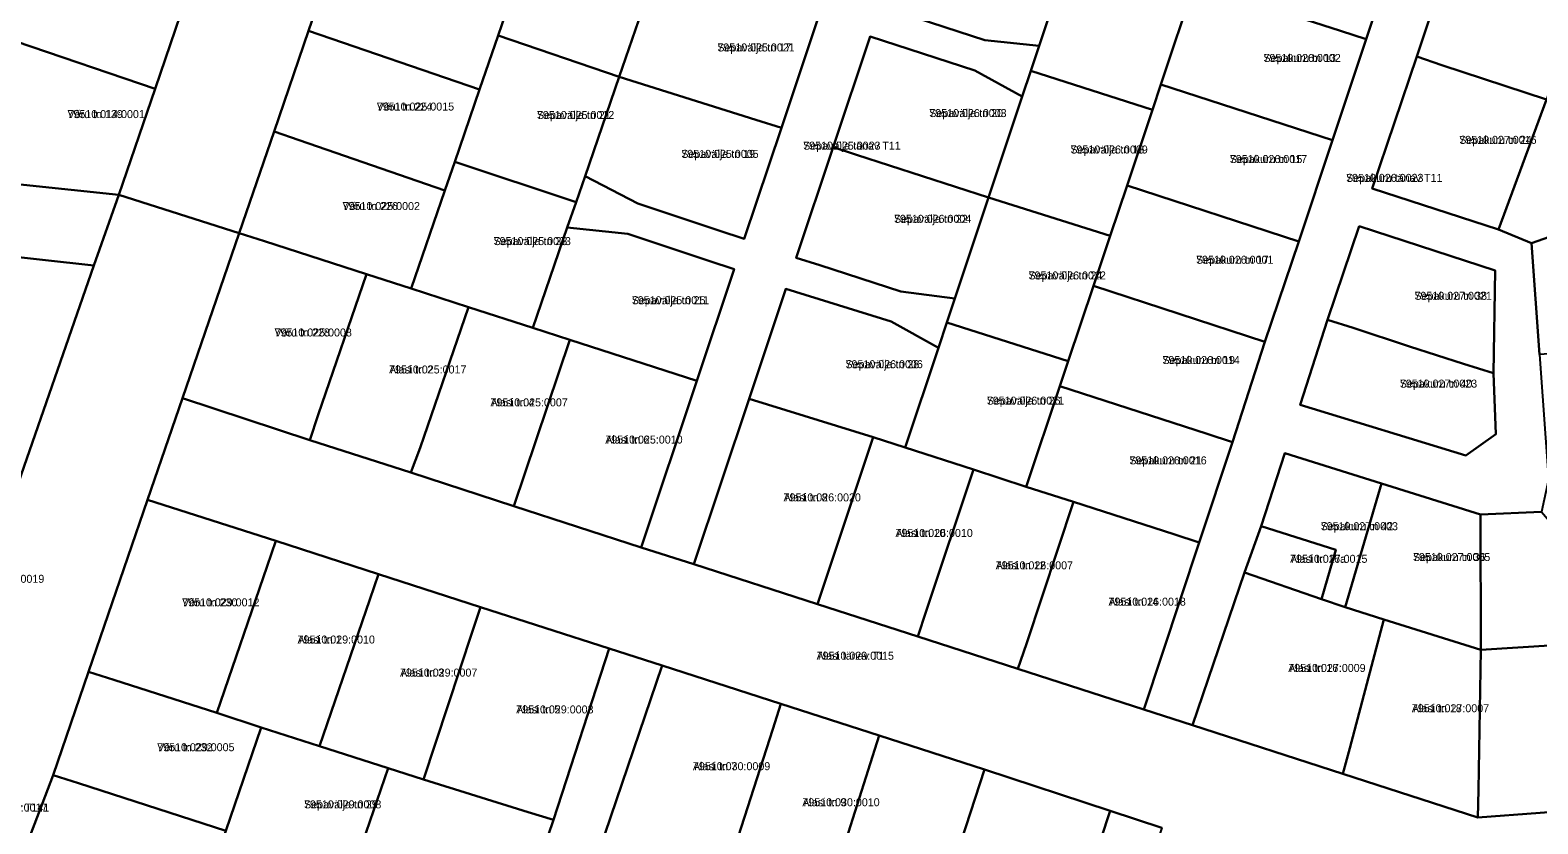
# Model space of a CAD drawing. Extents: x 643847 to 663718, y 6468443 to 6482775.
# Drawn here: x 658986.5 to 659269.3, y 6470648.8 to 6470797.7 of the extents above; entities that cross this region are included whole.
import ezdxf

# ---------------------------------------------------------------- set-up
doc = ezdxf.new("R2010")
doc.units = 0
for name, color, linetype in [('L_AADRESS', 7, 'Continuous'), ('PIIR', 7, 'Continuous'), ('TUNNUS', 7, 'Continuous')]:
    doc.layers.add(name, color=color, linetype=linetype)

msp = doc.modelspace()

# ---------------------------------------------------------------- linework, layer by layer
at = {"layer": 'PIIR'}
for points in [[(659093.31, 6470956.47), (659086.53, 6470937.12), (659080.25, 6470918.45), (659072.16, 6470894.63), (659068.8, 6470885.14), (659058.1, 6470854.01), (659051.7, 6470835.39), (659045.2, 6470816.47), (659038.7, 6470797.55), (659032.2, 6470778.64), (659025.68, 6470759.62), (659003.09, 6470766.8), (659009.88, 6470786.67), (659018.48, 6470811.86), (659025.39, 6470832.1), (659033.14, 6470854.81), (659042.51, 6470882.25), (659051.73, 6470909.22), (659059.58, 6470932.21), (659070.24, 6470963.44)], [(659150.31, 6470800.74), (659165.53, 6470795.81), (659175.71, 6470794.72), (659174.15, 6470790.03), (659172.54, 6470785.23), (659163.63, 6470790.12), (659144.02, 6470796.47), (659137.08, 6470775.71), (659130.16, 6470755), (659134.55, 6470753.58), (659149.77, 6470748.64), (659159.92, 6470747.37), (659158.41, 6470742.82), (659156.83, 6470738.07), (659147.93, 6470743.05), (659128.21, 6470749.16), (659121.31, 6470728.51), (659110.95, 6470697.5), (659101.09, 6470700.63), (659111.51, 6470731.89), (659118.5, 6470752.82), (659113.76, 6470754.4), (659098.59, 6470759.48), (659087.21, 6470760.64), (659088.86, 6470765.39), (659090.54, 6470770.28), (659100.47, 6470765.16), (659115.65, 6470760.09), (659120.4, 6470758.51), (659127.36, 6470779.36), (659134.26, 6470800.01)], [(658983.22, 6470709.77), (658998.39, 6470753.53), (659003.09, 6470766.8), (659025.68, 6470759.62), (659015.04, 6470728.65), (659008.5, 6470709.6), (658997.42, 6470677.35), (658990.76, 6470657.95), (658983.48, 6470638.76)], [(659198.74, 6470648.08), (659189.03, 6470651.25), (659165.44, 6470659.01), (659145.7, 6470665.38), (659127.28, 6470671.31), (659105, 6470678.48), (659095.04, 6470681.69), (659070.96, 6470689.47), (659051.8, 6470695.64), (659032.52, 6470701.86), (659008.5, 6470709.6), (659015.04, 6470728.65), (659038.89, 6470720.79), (659057.89, 6470714.69), (659077.18, 6470708.41), (659101.09, 6470700.63), (659110.95, 6470697.5), (659134.16, 6470690), (659152.97, 6470683.93), (659171.75, 6470677.86), (659195.33, 6470670.26), (659204.51, 6470667.3), (659232.71, 6470658.18), (659258.01, 6470650.01), (659281.4, 6470651.73)], [(659077.64, 6470629), (659084.65, 6470649.54), (659095.04, 6470681.69), (659105, 6470678.48), (659094.27, 6470646.86)]]:
    msp.add_lwpolyline(points, dxfattribs=at)
for points in [[(659237.03, 6470795.98), (659232.27, 6470797.52), (659213.91, 6470803.48), (659222.53, 6470830.11), (659224.07, 6470834.87), (659247.42, 6470827.29)], [(659009.88, 6470786.67), (658983.85, 6470795.56), (658982.56, 6470791.78), (658974.24, 6470794.62), (658973.43, 6470792.25), (658956.87, 6470797.9), (658967.57, 6470829.24), (658992.46, 6470820.75), (659018.48, 6470811.86)], [(659237.03, 6470795.98), (659247.42, 6470827.29), (659256.98, 6470824.2), (659246.54, 6470792.72), (659238.16, 6470768), (659261.9, 6470760.31), (659268.06, 6470757.75), (659269.58, 6470736.81), (659271.28, 6470713.37), (659269.94, 6470707.34), (659258.52, 6470706.83), (659239.92, 6470712.65), (659221.79, 6470718.31), (659217.36, 6470704.62), (659214.26, 6470695.97), (659204.51, 6470667.3), (659195.33, 6470670.26), (659205.72, 6470701.58), (659211.97, 6470720.41), (659218.03, 6470739.2), (659224.44, 6470758.02), (659230.74, 6470777.01)], [(659145.89, 6470802.17), (659152.92, 6470823.23), (659157.35, 6470821.8), (659176.24, 6470815.68), (659182.09, 6470813.79), (659175.71, 6470794.72), (659165.53, 6470795.81), (659150.31, 6470800.74)], [(659256.98, 6470824.2), (659281.15, 6470816.36), (659279.62, 6470811.6), (659270.89, 6470784.68), (659251.22, 6470791.08), (659246.54, 6470792.72)], [(659105.12, 6470812.76), (659096.94, 6470788.92), (659074.24, 6470796.67), (659082.29, 6470820.15)], [(659045.2, 6470816.47), (659049.92, 6470814.85), (659077.25, 6470805.46), (659074.24, 6470796.67), (659070.76, 6470786.54), (659038.7, 6470797.55)], [(659195.08, 6470809.58), (659204.88, 6470806.41), (659198.55, 6470787.48), (659196.96, 6470782.73), (659174.15, 6470790.03), (659175.71, 6470794.72), (659182.09, 6470813.79)], [(659134.26, 6470800.01), (659127.36, 6470779.36), (659122.59, 6470780.86), (659096.94, 6470788.92), (659103.49, 6470808), (659114.34, 6470806.68), (659129.52, 6470801.6)], [(659230.74, 6470777.01), (659198.55, 6470787.48), (659204.88, 6470806.41), (659213.91, 6470803.48), (659232.27, 6470797.52), (659237.03, 6470795.98)], [(659038.7, 6470797.55), (659070.76, 6470786.54), (659066.09, 6470772.95), (659064.26, 6470767.62), (659036.92, 6470777.01), (659032.2, 6470778.64)], [(659096.94, 6470788.92), (659090.54, 6470770.28), (659088.86, 6470765.39), (659066.09, 6470772.95), (659070.76, 6470786.54), (659074.24, 6470796.67)], [(659003.09, 6470766.8), (658975.03, 6470769.73), (658982.56, 6470791.78), (658983.85, 6470795.56), (659009.88, 6470786.67)], [(659144.02, 6470796.47), (659163.63, 6470790.12), (659172.54, 6470785.23), (659166.21, 6470766.27), (659141.47, 6470774.28), (659137.08, 6470775.71)], [(659246.54, 6470792.72), (659251.22, 6470791.08), (659270.89, 6470784.68), (659261.9, 6470760.31), (659238.16, 6470768)], [(659120.4, 6470758.51), (659115.65, 6470760.09), (659100.47, 6470765.16), (659090.54, 6470770.28), (659096.94, 6470788.92), (659122.59, 6470780.86), (659127.36, 6470779.36)], [(659196.96, 6470782.73), (659192.22, 6470768.51), (659189.06, 6470759.08), (659166.21, 6470766.27), (659172.54, 6470785.23), (659174.15, 6470790.03)], [(659224.44, 6470758.02), (659192.22, 6470768.51), (659196.96, 6470782.73), (659198.55, 6470787.48), (659230.74, 6470777.01)], [(658839.94, 6470784.5), (658932.96, 6470776.66), (658951.36, 6470772.19), (658975.03, 6470769.73), (659003.09, 6470766.8), (658998.39, 6470753.53), (658930.96, 6470760.99), (658919.79, 6470762.66), (658900.37, 6470764.47), (658895.41, 6470767.26), (658859.85, 6470769.74), (658849.31, 6470770.31), (658807.18, 6470768.34), (658771.92, 6470766.68), (658763.13, 6470766.29), (658761.21, 6470780.3), (658777.32, 6470781.36), (658804.6, 6470783.22)], [(659261.9, 6470760.31), (659270.89, 6470784.68), (659290.21, 6470778.43), (659292.41, 6470778.14), (659292.93, 6470766.46), (659268.06, 6470757.75)], [(659032.2, 6470778.64), (659036.92, 6470777.01), (659064.26, 6470767.62), (659057.93, 6470749.21), (659049.56, 6470751.91), (659030.43, 6470758.09), (659025.68, 6470759.62)], [(659137.08, 6470775.71), (659141.47, 6470774.28), (659166.21, 6470766.27), (659159.92, 6470747.37), (659149.77, 6470748.64), (659134.55, 6470753.58), (659130.16, 6470755)], [(659087.21, 6470760.64), (659080.77, 6470741.82), (659068.68, 6470745.72), (659057.93, 6470749.21), (659064.26, 6470767.62), (659066.09, 6470772.95), (659088.86, 6470765.39)], [(659218.03, 6470739.2), (659185.91, 6470749.69), (659189.06, 6470759.08), (659192.22, 6470768.51), (659224.44, 6470758.02)], [(659159.92, 6470747.37), (659166.21, 6470766.27), (659189.06, 6470759.08), (659185.91, 6470749.69), (659181.18, 6470735.56), (659158.41, 6470742.82)], [(659268.06, 6470757.75), (659292.93, 6470766.46), (659293.93, 6470754.63), (659294.83, 6470738.64), (659269.58, 6470736.81)], [(658930.96, 6470760.99), (658998.39, 6470753.53), (658983.22, 6470709.77), (658976.23, 6470710.52), (658925.46, 6470715.92), (658925.74, 6470720.46), (658929.04, 6470746.11)], [(659111.51, 6470731.89), (659087.71, 6470739.58), (659080.77, 6470741.82), (659087.21, 6470760.64), (659098.59, 6470759.48), (659113.76, 6470754.4), (659118.5, 6470752.82)], [(659235.75, 6470760.9), (659229.81, 6470743.37), (659224.66, 6470727.42), (659255.75, 6470717.9), (659261.35, 6470721.89), (659260.96, 6470733.31), (659261.24, 6470752.58)], [(659235.75, 6470760.9), (659261.24, 6470752.58), (659260.96, 6470733.31), (659255.29, 6470735.06), (659245.21, 6470738.35), (659234.6, 6470741.81), (659229.81, 6470743.37)], [(659025.68, 6470759.62), (659030.43, 6470758.09), (659049.56, 6470751.91), (659040.51, 6470725.52), (659038.89, 6470720.79), (659015.04, 6470728.65)], [(659038.89, 6470720.79), (659040.51, 6470725.52), (659049.56, 6470751.91), (659057.93, 6470749.21), (659068.68, 6470745.72), (659059.64, 6470719.33), (659057.89, 6470714.69)], [(659128.21, 6470749.16), (659147.93, 6470743.05), (659156.83, 6470738.07), (659150.61, 6470719.37), (659144.6, 6470721.31), (659121.31, 6470728.51)], [(659211.97, 6470720.41), (659207.21, 6470721.95), (659179.62, 6470730.87), (659181.18, 6470735.56), (659185.91, 6470749.69), (659218.03, 6470739.2)], [(659057.89, 6470714.69), (659059.64, 6470719.33), (659068.68, 6470745.72), (659080.77, 6470741.82), (659087.71, 6470739.58), (659077.18, 6470708.41)], [(659224.66, 6470727.42), (659229.81, 6470743.37), (659234.6, 6470741.81), (659245.21, 6470738.35), (659255.29, 6470735.06), (659260.96, 6470733.31), (659261.35, 6470721.89), (659255.75, 6470717.9)], [(659150.61, 6470719.37), (659156.83, 6470738.07), (659158.41, 6470742.82), (659181.18, 6470735.56), (659179.62, 6470730.87), (659173.3, 6470712.04), (659163.39, 6470715.25)], [(659077.18, 6470708.41), (659087.71, 6470739.58), (659111.51, 6470731.89), (659101.09, 6470700.63)], [(659205.72, 6470701.58), (659200.96, 6470703.12), (659182.18, 6470709.18), (659173.3, 6470712.04), (659179.62, 6470730.87), (659207.21, 6470721.95), (659211.97, 6470720.41)], [(659110.95, 6470697.5), (659121.31, 6470728.51), (659144.6, 6470721.31), (659134.16, 6470690)], [(659134.16, 6470690), (659144.6, 6470721.31), (659150.61, 6470719.37), (659163.39, 6470715.25), (659154.54, 6470688.67), (659152.97, 6470683.93)], [(659221.79, 6470718.31), (659239.92, 6470712.65), (659233.13, 6470689.47), (659228.66, 6470690.92), (659231.39, 6470700.23), (659217.36, 6470704.62)], [(659152.97, 6470683.93), (659154.54, 6470688.67), (659163.39, 6470715.25), (659173.3, 6470712.04), (659182.18, 6470709.18), (659173.33, 6470682.6), (659171.75, 6470677.86)], [(659258.52, 6470706.83), (659258.54, 6470681.43), (659240.39, 6470687.11), (659233.13, 6470689.47), (659239.92, 6470712.65)], [(659008.5, 6470709.6), (659032.52, 6470701.86), (659030.9, 6470697.13), (659021.45, 6470669.6), (659002.18, 6470675.81), (658997.42, 6470677.35)], [(659171.75, 6470677.86), (659173.33, 6470682.6), (659182.18, 6470709.18), (659200.96, 6470703.12), (659205.72, 6470701.58), (659195.33, 6470670.26)], [(659269.94, 6470707.34), (659290.47, 6470683.48), (659279.4, 6470682.77), (659258.54, 6470681.43), (659258.52, 6470706.83)], [(659214.26, 6470695.97), (659217.36, 6470704.62), (659231.39, 6470700.23), (659228.66, 6470690.92)], [(659051.8, 6470695.64), (659050.17, 6470690.91), (659040.73, 6470663.4), (659029.82, 6470666.9), (659021.45, 6470669.6), (659030.9, 6470697.13), (659032.52, 6470701.86)], [(659070.96, 6470689.47), (659069.38, 6470684.73), (659060.22, 6470657.14), (659053.62, 6470659.23), (659040.73, 6470663.4), (659050.17, 6470690.91), (659051.8, 6470695.64)], [(659204.51, 6470667.3), (659214.26, 6470695.97), (659228.66, 6470690.92), (659233.13, 6470689.47), (659240.39, 6470687.11), (659234, 6470663.01), (659232.71, 6470658.18)], [(659095.04, 6470681.69), (659084.65, 6470649.54), (659079.88, 6470651.02), (659060.22, 6470657.14), (659069.38, 6470684.73), (659070.96, 6470689.47)], [(659232.71, 6470658.18), (659234, 6470663.01), (659240.39, 6470687.11), (659258.54, 6470681.43), (659258.1, 6470655.22), (659258.01, 6470650.01)], [(659258.01, 6470650.01), (659258.1, 6470655.22), (659258.54, 6470681.43), (659279.4, 6470682.77), (659281.08, 6470656.72), (659281.4, 6470651.73)], [(659127.28, 6470671.31), (659125.75, 6470666.55), (659116.89, 6470638.99), (659098.96, 6470645.23), (659094.27, 6470646.86), (659105, 6470678.48)], [(658997.42, 6470677.35), (659002.18, 6470675.81), (659021.45, 6470669.6), (659029.82, 6470666.9), (659023.17, 6470647.5), (658995.52, 6470656.42), (658990.76, 6470657.95)], [(659145.7, 6470665.38), (659135.41, 6470632.87), (659122.74, 6470636.96), (659116.89, 6470638.99), (659125.75, 6470666.55), (659127.28, 6470671.31)], [(659022.03, 6470644.2), (659023.17, 6470647.5), (659029.82, 6470666.9), (659040.73, 6470663.4), (659053.62, 6470659.23), (659047.45, 6470641.25), (659045.82, 6470636.53)], [(659145.7, 6470665.38), (659165.44, 6470659.01), (659154.88, 6470626.58), (659145.6, 6470629.59), (659135.41, 6470632.87)], [(659084.65, 6470649.54), (659077.64, 6470629), (659053.28, 6470637.66), (659047.45, 6470641.25), (659053.62, 6470659.23), (659060.22, 6470657.14), (659079.88, 6470651.02)], [(659189.03, 6470651.25), (659178.39, 6470619.01), (659173.67, 6470620.53), (659154.88, 6470626.58), (659165.44, 6470659.01)], [(658990.76, 6470657.95), (658995.52, 6470656.42), (659023.17, 6470647.5), (659022.03, 6470644.2), (659016.46, 6470628.13), (658988.85, 6470637.03), (658983.48, 6470638.76)], [(659178.39, 6470619.01), (659189.03, 6470651.25), (659198.74, 6470648.08), (659188.75, 6470618.73), (659181.86, 6470597.93), (659174.82, 6470576.74), (659169.18, 6470559.52), (659163.48, 6470542.45), (659156.81, 6470522.48), (659147.93, 6470495.87), (659150.64, 6470490.41), (659154.77, 6470488.75), (659132.95, 6470487.99), (659135.42, 6470490.03), (659143.17, 6470512.79), (659151.54, 6470537.87), (659154.89, 6470548.29), (659159.5, 6470562.37), (659165.99, 6470581.41), (659172.19, 6470600.2)]]:
    msp.add_lwpolyline(points, close=True, dxfattribs=at)

# ---------------------------------------------------------------- texts
at = {"layer": 'L_AADRESS'}
for s, p in [('Sepavälja tn 17', (659115.36, 6470793.68)), ('Sepakuru tn 13', (659217.79, 6470791.71)), ('Võru tn 139', (658993.47, 6470781.18)), ('Võru tn 224', (659051.48, 6470782.59)), ('Sepavälja tn 21', (659081.52, 6470781.01)), ('Sepavälja tn 20', (659155.11, 6470781.37)), ('Sepavälja tänav T11', (659131.46, 6470775.26)), ('Sepakuru tn 24', (659254.52, 6470776.35)), ('Sepavälja tn 19', (659108.6, 6470773.72)), ('Sepavälja tn 18', (659181.59, 6470774.54)), ('Sepakuru tn 15', (659211.48, 6470772.75)), ('Sepakuru tänav T11', (659233.3, 6470769.22)), ('Võru tn 226', (659045.07, 6470763.93)), ('Sepavälja tn 22', (659148.49, 6470761.54)), ('Sepavälja tn 23', (659073.39, 6470757.36)), ('Sepakuru tn 17', (659205.16, 6470753.86)), ('Sepavälja tn 24', (659173.73, 6470750.92)), ('Sepakuru tn 38', (659246.12, 6470747.1)), ('Sepavälja tn 25', (659099.3, 6470746.27)), ('Võru tn 228', (659032.3, 6470740.22)), ('Alasi tn 2', (659053.79, 6470733.28)), ('Sepavälja tn 28', (659139.4, 6470734.27)), ('Sepakuru tn 19', (659198.85, 6470735.05)), ('Sepakuru tn 40', (659243.37, 6470730.63)), ('Sepavälja tn 26', (659165.89, 6470727.44)), ('Alasi tn 4', (659072.8, 6470727.11)), ('Alasi tn 6', (659094.34, 6470720.13)), ('Sepakuru tn 21', (659192.64, 6470716.23)), ('Alasi tn 8', (659127.78, 6470709.29)), ('Alasi tn 10', (659148.77, 6470702.62)), ('Sepakuru tn 42', (659228.52, 6470703.89)), ('Alasi tn 12', (659167.57, 6470696.55)), ('Alasi tn 16a', (659222.79, 6470697.77)), ('Sepakuru tn 36', (659245.84, 6470698.1)), ('Võru tn 230', (659014.97, 6470689.6)), ('Alasi tn 14', (659188.73, 6470689.73)), ('Alasi tn 1', (659036.62, 6470682.63)), ('Alasi tänav T1', (659133.98, 6470679.59)), ('Alasi tn 3', (659055.84, 6470676.43)), ('Alasi tn 16', (659222.45, 6470677.3)), ('Alasi tn 5', (659077.63, 6470669.52)), ('Alasi tn 18', (659245.62, 6470669.74)), ('Võru tn 232', (659010.29, 6470662.43)), ('Alasi tn 7', (659110.78, 6470658.87)), ('Võru tänav T141', (658975.2, 6470651.11)), ('Sepavälja tn 29', (659037.83, 6470651.71)), ('Alasi tn 9', (659131.3, 6470652.11))]:
    msp.add_text(s, height=1.5, dxfattribs=at).set_placement(p)
at = {"layer": 'TUNNUS'}
for s, p in [('79510:025:0021', (659115.36, 6470793.68)), ('79510:026:0002', (659217.79, 6470791.71)), ('79510:014:0001', (658993.47, 6470781.18)), ('79510:025:0015', (659051.48, 6470782.59)), ('79510:025:0012', (659081.52, 6470781.01)), ('79510:026:0003', (659155.11, 6470781.37)), ('79510:025:0023', (659131.46, 6470775.26)), ('79510:027:0016', (659254.52, 6470776.35)), ('79510:025:0005', (659108.6, 6470773.72)), ('79510:026:0009', (659181.59, 6470774.54)), ('79510:026:0017', (659211.48, 6470772.75)), ('79510:026:0023', (659233.3, 6470769.22)), ('79510:025:0002', (659045.07, 6470763.93)), ('79510:026:0004', (659148.49, 6470761.54)), ('79510:025:0003', (659073.39, 6470757.36)), ('79510:026:0001', (659205.16, 6470753.86)), ('79510:026:0012', (659173.73, 6470750.92)), ('79510:027:0021', (659246.12, 6470747.1)), ('79510:025:0011', (659099.3, 6470746.27)), ('79510:025:0008', (659032.3, 6470740.22)), ('79510:025:0017', (659053.79, 6470733.28)), ('79510:026:0006', (659139.4, 6470734.27)), ('79510:026:0014', (659198.85, 6470735.05)), ('79510:027:0023', (659243.37, 6470730.63)), ('79510:026:0021', (659165.89, 6470727.44)), ('79510:025:0007', (659072.8, 6470727.11)), ('79510:025:0010', (659094.34, 6470720.13)), ('79510:026:0016', (659192.64, 6470716.23)), ('79510:026:0020', (659127.78, 6470709.29)), ('79510:026:0010', (659148.77, 6470702.62)), ('79510:027:0003', (659228.52, 6470703.89)), ('79510:026:0007', (659167.57, 6470696.55)), ('79510:027:0015', (659222.79, 6470697.77)), ('79510:027:0005', (659245.84, 6470698.1)), ('79510:016:0019', (658974.61, 6470694.02)), ('79510:029:0012', (659014.97, 6470689.6)), ('79510:026:0018', (659188.73, 6470689.73)), ('79510:029:0010', (659036.62, 6470682.63)), ('79510:029:0015', (659133.98, 6470679.59)), ('79510:029:0007', (659055.84, 6470676.43)), ('79510:027:0009', (659222.45, 6470677.3)), ('79510:029:0003', (659077.63, 6470669.52)), ('79510:027:0007', (659245.62, 6470669.74)), ('79510:029:0005', (659010.29, 6470662.43)), ('79510:030:0009', (659110.78, 6470658.87)), ('79510:029:0017', (658975.2, 6470651.11)), ('79510:029:0008', (659037.83, 6470651.71)), ('79510:030:0010', (659131.3, 6470652.11))]:
    msp.add_text(s, height=1.5, dxfattribs=at).set_placement(p)

doc.saveas('drawing.dxf')
